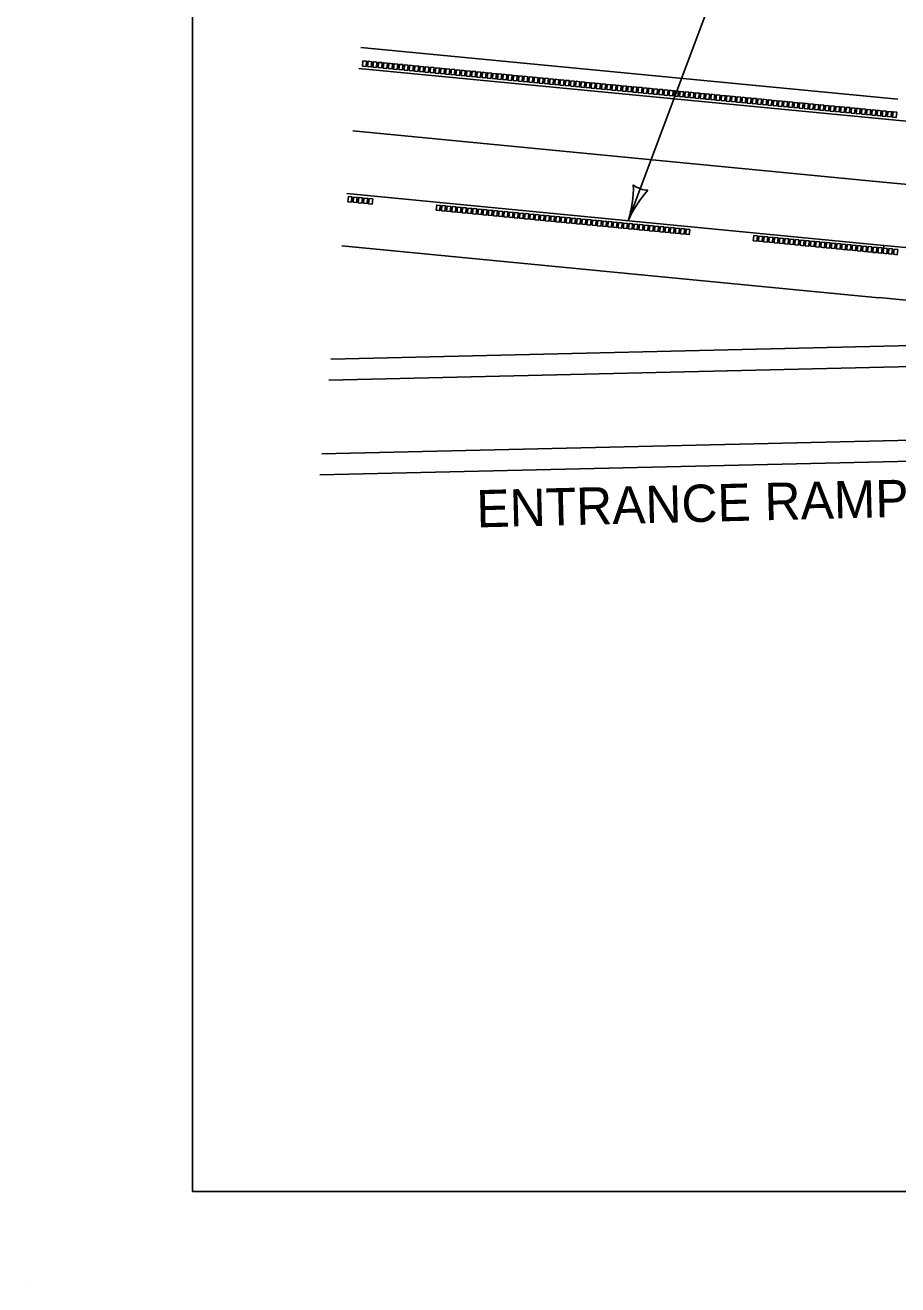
# Model space of a CAD drawing. Extents: x 49991.4 to 50021, y 49987.6 to 50011.4.
# Drawn here: x 49999.024 to 50000.896, y 49987.599 to 49990.3 of the extents above; entities that cross this region are included whole.
import ezdxf

# ---------------------------------------------------------------- set-up
doc = ezdxf.new("R2010")
doc.units = 0
for name, color, linetype in [('Level 1', 7, 'Continuous'), ('Level 2', 7, 'Continuous'), ('Level 3', 7, 'Continuous')]:
    doc.layers.add(name, color=color, linetype=linetype)

msp = doc.modelspace()

# ---------------------------------------------------------------- linework, layer by layer
at = {"layer": 'Level 1'}
for p, q in [((49999.7445, 49990.2519), (50000.8963, 49990.141)), ((49999.7402, 49990.207), (50000.892, 49990.0962)), ((49999.7273, 49990.0728), (50000.8791, 49989.9618)), ((49999.7143, 49989.9384), (50000.8661, 49989.8274)), ((49999.7035, 49989.8264), (50000.8553, 49989.7154)), ((50000.8659, 49989.8216), (50000.8649, 49989.8105)), ((50000.8665, 49989.8274), (50000.8659, 49989.8216)), ((50000.8659, 49989.8216), (50000.8737, 49989.8209)), ((50000.8737, 49989.8209), (50000.8726, 49989.8097)), ((50000.8771, 49989.8206), (50000.876, 49989.8094)), ((50000.8771, 49989.8206), (50000.8848, 49989.8198)), ((50000.8848, 49989.8198), (50000.8838, 49989.8087)), ((50000.8882, 49989.8195), (50000.8871, 49989.8084)), ((50000.8882, 49989.8195), (50000.896, 49989.8188)), ((50000.896, 49989.8188), (50000.8949, 49989.8076)), ((50000.8649, 49989.8105), (50000.8726, 49989.8097)), ((50000.876, 49989.8094), (50000.8838, 49989.8087)), ((50000.8871, 49989.8084), (50000.8949, 49989.8076)), ((49999.6802, 49989.5838), (50001.8012, 49989.633)), ((49999.6759, 49989.5388), (50001.654, 49989.5846)), ((49999.6607, 49989.3808), (50001.6577, 49989.427)), ((49999.6563, 49989.3358), (50001.6587, 49989.382)), ((49999.0245, 49987.5988), (49999.0245, 49987.5988))]:
    msp.add_line(p, q, dxfattribs=at)
for points in [[(49999.3835, 49998.9992), (50016.7501, 49998.9992), (50016.7501, 49987.7988), (49999.3835, 49987.7988)], [(49999.748, 49990.2121), (49999.7557, 49990.2113), (49999.7568, 49990.2225), (49999.749, 49990.2232)], [(49999.7591, 49990.211), (49999.7669, 49990.2103), (49999.7679, 49990.2214), (49999.7602, 49990.2222)], [(49999.7702, 49990.2099), (49999.778, 49990.2092), (49999.7791, 49990.2203), (49999.7713, 49990.2211)], [(49999.7814, 49990.2089), (49999.7892, 49990.2081), (49999.7902, 49990.2193), (49999.7825, 49990.22)], [(49999.7925, 49990.2078), (49999.8003, 49990.2071), (49999.8014, 49990.2182), (49999.7936, 49990.219)], [(49999.8037, 49990.2067), (49999.8115, 49990.206), (49999.8125, 49990.2171), (49999.8048, 49990.2179)], [(49999.8148, 49990.2057), (49999.8226, 49990.2049), (49999.8237, 49990.2161), (49999.8159, 49990.2168)], [(49999.826, 49990.2046), (49999.8338, 49990.2038), (49999.8348, 49990.215), (49999.8271, 49990.2157)], [(49999.8371, 49990.2035), (49999.8449, 49990.2028), (49999.846, 49990.2139), (49999.8382, 49990.2147)], [(49999.8483, 49990.2024), (49999.8561, 49990.2017), (49999.8571, 49990.2128), (49999.8494, 49990.2136)], [(49999.8594, 49990.2014), (49999.8672, 49990.2006), (49999.8683, 49990.2118), (49999.8605, 49990.2125)], [(49999.8706, 49990.2003), (49999.8784, 49990.1995), (49999.8794, 49990.2107), (49999.8717, 49990.2114)], [(49999.8817, 49990.1992), (49999.8895, 49990.1985), (49999.8906, 49990.2096), (49999.8828, 49990.2104)], [(49999.8929, 49990.1982), (49999.9006, 49990.1974), (49999.9017, 49990.2086), (49999.894, 49990.2093)], [(49999.904, 49990.1971), (49999.9118, 49990.1963), (49999.9129, 49990.2075), (49999.9051, 49990.2082)], [(49999.9152, 49990.196), (49999.9229, 49990.1953), (49999.924, 49990.2064), (49999.9163, 49990.2072)], [(49999.9263, 49990.1949), (49999.9341, 49990.1942), (49999.9352, 49990.2053), (49999.9274, 49990.2061)], [(49999.9375, 49990.1939), (49999.9452, 49990.1931), (49999.9463, 49990.2043), (49999.9386, 49990.205)], [(49999.9486, 49990.1928), (49999.9564, 49990.192), (49999.9575, 49990.2032), (49999.9497, 49990.2039)], [(49999.9598, 49990.1917), (49999.9675, 49990.191), (49999.9686, 49990.2021), (49999.9608, 49990.2029)], [(49999.9709, 49990.1906), (49999.9787, 49990.1899), (49999.9798, 49990.201), (49999.972, 49990.2018)], [(49999.9821, 49990.1896), (49999.9898, 49990.1888), (49999.9909, 49990.2), (49999.9831, 49990.2007)], [(49999.9932, 49990.1885), (50000.001, 49990.1878), (50000.0021, 49990.1989), (49999.9943, 49990.1996)], [(50000.0044, 49990.1874), (50000.0121, 49990.1867), (50000.0132, 49990.1978), (50000.0054, 49990.1986)], [(50000.0155, 49990.1864), (50000.0233, 49990.1856), (50000.0244, 49990.1968), (50000.0166, 49990.1975)], [(50000.0267, 49990.1853), (50000.0344, 49990.1845), (50000.0355, 49990.1957), (50000.0277, 49990.1964)], [(50000.0378, 49990.1842), (50000.0456, 49990.1835), (50000.0467, 49990.1946), (50000.0389, 49990.1954)], [(50000.049, 49990.1831), (50000.0567, 49990.1824), (50000.0578, 49990.1935), (50000.05, 49990.1943)], [(50000.0601, 49990.1821), (50000.0679, 49990.1813), (50000.0689, 49990.1925), (50000.0612, 49990.1932)], [(50000.0713, 49990.181), (50000.079, 49990.1802), (50000.0801, 49990.1914), (50000.0723, 49990.1921)], [(50000.0824, 49990.1799), (50000.0902, 49990.1792), (50000.0912, 49990.1903), (50000.0835, 49990.1911)], [(50000.0936, 49990.1788), (50000.1013, 49990.1781), (50000.1024, 49990.1892), (50000.0946, 49990.19)], [(50000.1047, 49990.1778), (50000.1125, 49990.177), (50000.1135, 49990.1882), (50000.1058, 49990.1889)], [(50000.1159, 49990.1767), (50000.1236, 49990.176), (50000.1247, 49990.1871), (50000.1169, 49990.1879)], [(50000.127, 49990.1756), (50000.1348, 49990.1749), (50000.1358, 49990.186), (50000.1281, 49990.1868)], [(50000.1382, 49990.1746), (50000.1459, 49990.1738), (50000.147, 49990.185), (50000.1392, 49990.1857)], [(50000.1493, 49990.1735), (50000.1571, 49990.1727), (50000.1581, 49990.1839), (50000.1504, 49990.1846)], [(50000.1604, 49990.1724), (50000.1682, 49990.1717), (50000.1693, 49990.1828), (50000.1615, 49990.1836)], [(50000.1716, 49990.1713), (50000.1794, 49990.1706), (50000.1804, 49990.1817), (50000.1727, 49990.1825)], [(50000.1827, 49990.1703), (50000.1905, 49990.1695), (50000.1916, 49990.1807), (50000.1838, 49990.1814)], [(50000.1939, 49990.1692), (50000.2017, 49990.1684), (50000.2027, 49990.1796), (50000.195, 49990.1803)], [(50000.205, 49990.1681), (50000.2128, 49990.1674), (50000.2139, 49990.1785), (50000.2061, 49990.1793)], [(50000.2162, 49990.167), (50000.224, 49990.1663), (50000.225, 49990.1774), (50000.2173, 49990.1782)], [(50000.2273, 49990.166), (50000.2351, 49990.1652), (50000.2362, 49990.1764), (50000.2284, 49990.1771)], [(50000.2385, 49990.1649), (50000.2463, 49990.1642), (50000.2473, 49990.1753), (50000.2396, 49990.1761)], [(50000.2496, 49990.1638), (50000.2574, 49990.1631), (50000.2585, 49990.1742), (50000.2507, 49990.175)], [(50000.2608, 49990.1628), (50000.2685, 49990.162), (50000.2696, 49990.1732), (50000.2619, 49990.1739)], [(50000.2719, 49990.1617), (50000.2797, 49990.1609), (50000.2808, 49990.1721), (50000.273, 49990.1728)], [(50000.2831, 49990.1606), (50000.2908, 49990.1599), (50000.2919, 49990.171), (50000.2842, 49990.1718)], [(50000.2942, 49990.1595), (50000.302, 49990.1588), (50000.3031, 49990.1699), (50000.2953, 49990.1707)], [(50000.3054, 49990.1585), (50000.3131, 49990.1577), (50000.3142, 49990.1689), (50000.3065, 49990.1696)], [(50000.3165, 49990.1574), (50000.3243, 49990.1566), (50000.3254, 49990.1678), (50000.3176, 49990.1685)], [(50000.3277, 49990.1563), (50000.3354, 49990.1556), (50000.3365, 49990.1667), (50000.3288, 49990.1675)], [(50000.3388, 49990.1553), (50000.3466, 49990.1545), (50000.3477, 49990.1657), (50000.3399, 49990.1664)], [(50000.35, 49990.1542), (50000.3577, 49990.1534), (50000.3588, 49990.1646), (50000.351, 49990.1653)], [(50000.3611, 49990.1531), (50000.3689, 49990.1524), (50000.37, 49990.1635), (50000.3622, 49990.1643)], [(50000.3723, 49990.152), (50000.38, 49990.1513), (50000.3811, 49990.1624), (50000.3733, 49990.1632)], [(50000.3834, 49990.151), (50000.3912, 49990.1502), (50000.3923, 49990.1614), (50000.3845, 49990.1621)], [(50000.3946, 49990.1499), (50000.4023, 49990.1491), (50000.4034, 49990.1603), (50000.3956, 49990.161)], [(50000.4057, 49990.1488), (50000.4135, 49990.1481), (50000.4146, 49990.1592), (50000.4068, 49990.16)], [(50000.4169, 49990.1477), (50000.4246, 49990.147), (50000.4257, 49990.1581), (50000.4179, 49990.1589)], [(50000.428, 49990.1467), (50000.4358, 49990.1459), (50000.4369, 49990.1571), (50000.4291, 49990.1578)], [(50000.4392, 49990.1456), (50000.4469, 49990.1449), (50000.448, 49990.156), (50000.4402, 49990.1567)], [(50000.4503, 49990.1445), (50000.4581, 49990.1438), (50000.4591, 49990.1549), (50000.4514, 49990.1557)], [(50000.4615, 49990.1435), (50000.4692, 49990.1427), (50000.4703, 49990.1539), (50000.4625, 49990.1546)], [(50000.4726, 49990.1424), (50000.4804, 49990.1416), (50000.4814, 49990.1528), (50000.4737, 49990.1535)], [(50000.4838, 49990.1413), (50000.4915, 49990.1406), (50000.4926, 49990.1517), (50000.4848, 49990.1525)], [(50000.4949, 49990.1402), (50000.5027, 49990.1395), (50000.5037, 49990.1506), (50000.496, 49990.1514)], [(50000.5061, 49990.1392), (50000.5138, 49990.1384), (50000.5149, 49990.1496), (50000.5071, 49990.1503)], [(50000.5172, 49990.1381), (50000.525, 49990.1373), (50000.526, 49990.1485), (50000.5183, 49990.1492)], [(50000.5283, 49990.137), (50000.5361, 49990.1363), (50000.5372, 49990.1474), (50000.5294, 49990.1482)], [(50000.5395, 49990.1359), (50000.5473, 49990.1352), (50000.5483, 49990.1463), (50000.5406, 49990.1471)], [(50000.5506, 49990.1349), (50000.5584, 49990.1341), (50000.5595, 49990.1453), (50000.5517, 49990.146)], [(50000.5618, 49990.1338), (50000.5696, 49990.1331), (50000.5706, 49990.1442), (50000.5629, 49990.145)], [(50000.5729, 49990.1327), (50000.5807, 49990.132), (50000.5818, 49990.1431), (50000.574, 49990.1439)], [(50000.5841, 49990.1317), (50000.5919, 49990.1309), (50000.5929, 49990.1421), (50000.5852, 49990.1428)], [(50000.5952, 49990.1306), (50000.603, 49990.1298), (50000.6041, 49990.141), (50000.5963, 49990.1417)], [(50000.6064, 49990.1295), (50000.6142, 49990.1288), (50000.6152, 49990.1399), (50000.6075, 49990.1407)], [(50000.6175, 49990.1284), (50000.6253, 49990.1277), (50000.6264, 49990.1388), (50000.6186, 49990.1396)], [(50000.6287, 49990.1274), (50000.6365, 49990.1266), (50000.6375, 49990.1378), (50000.6298, 49990.1385)], [(50000.6398, 49990.1263), (50000.6476, 49990.1255), (50000.6487, 49990.1367), (50000.6409, 49990.1374)], [(50000.651, 49990.1252), (50000.6587, 49990.1245), (50000.6598, 49990.1356), (50000.6521, 49990.1364)], [(50000.6621, 49990.1242), (50000.6699, 49990.1234), (50000.671, 49990.1346), (50000.6632, 49990.1353)], [(50000.6733, 49990.1231), (50000.681, 49990.1223), (50000.6821, 49990.1335), (50000.6744, 49990.1342)], [(50000.6844, 49990.122), (50000.6922, 49990.1213), (50000.6933, 49990.1324), (50000.6855, 49990.1332)], [(50000.6956, 49990.1209), (50000.7033, 49990.1202), (50000.7044, 49990.1313), (50000.6967, 49990.1321)], [(50000.7067, 49990.1199), (50000.7145, 49990.1191), (50000.7156, 49990.1303), (50000.7078, 49990.131)], [(50000.7179, 49990.1188), (50000.7256, 49990.118), (50000.7267, 49990.1292), (50000.7189, 49990.1299)], [(50000.729, 49990.1177), (50000.7368, 49990.117), (50000.7379, 49990.1281), (50000.7301, 49990.1289)], [(50000.7402, 49990.1166), (50000.7479, 49990.1159), (50000.749, 49990.127), (50000.7412, 49990.1278)], [(50000.7513, 49990.1156), (50000.7591, 49990.1148), (50000.7602, 49990.126), (50000.7524, 49990.1267)], [(50000.7625, 49990.1145), (50000.7702, 49990.1138), (50000.7713, 49990.1249), (50000.7635, 49990.1256)], [(50000.7736, 49990.1134), (50000.7814, 49990.1127), (50000.7825, 49990.1238), (50000.7747, 49990.1246)], [(50000.7848, 49990.1124), (50000.7925, 49990.1116), (50000.7936, 49990.1228), (50000.7858, 49990.1235)], [(50000.7959, 49990.1113), (50000.8037, 49990.1105), (50000.8048, 49990.1217), (50000.797, 49990.1224)], [(50000.8071, 49990.1102), (50000.8148, 49990.1095), (50000.8159, 49990.1206), (50000.8081, 49990.1214)], [(50000.8182, 49990.1091), (50000.826, 49990.1084), (50000.827, 49990.1195), (50000.8193, 49990.1203)], [(50000.8294, 49990.1081), (50000.8371, 49990.1073), (50000.8382, 49990.1185), (50000.8304, 49990.1192)], [(50000.8405, 49990.107), (50000.8483, 49990.1062), (50000.8493, 49990.1174), (50000.8416, 49990.1181)], [(50000.8517, 49990.1059), (50000.8594, 49990.1052), (50000.8605, 49990.1163), (50000.8527, 49990.1171)], [(50000.8628, 49990.1048), (50000.8706, 49990.1041), (50000.8716, 49990.1152), (50000.8639, 49990.116)], [(50000.874, 49990.1038), (50000.8817, 49990.103), (50000.8828, 49990.1142), (50000.875, 49990.1149)], [(50000.8851, 49990.1027), (50000.8929, 49990.102), (50000.8939, 49990.1131), (50000.8862, 49990.1139)], [(49999.7166, 49989.9212), (49999.7244, 49989.9204), (49999.7254, 49989.9316), (49999.7177, 49989.9323)], [(49999.7278, 49989.9201), (49999.7355, 49989.9193), (49999.7366, 49989.9305), (49999.7288, 49989.9312)], [(49999.7389, 49989.919), (49999.7467, 49989.9183), (49999.7477, 49989.9294), (49999.74, 49989.9302)], [(49999.7501, 49989.9179), (49999.7578, 49989.9172), (49999.7589, 49989.9283), (49999.7511, 49989.9291)], [(49999.7612, 49989.9169), (49999.769, 49989.9161), (49999.77, 49989.9273), (49999.7623, 49989.928)], [(49999.9061, 49989.9029), (49999.9139, 49989.9021), (49999.915, 49989.9133), (49999.9072, 49989.914)], [(49999.9173, 49989.9018), (49999.925, 49989.9011), (49999.9261, 49989.9122), (49999.9184, 49989.913)], [(49999.9284, 49989.9007), (49999.9362, 49989.9), (49999.9373, 49989.9111), (49999.9295, 49989.9119)], [(49999.9396, 49989.8997), (49999.9473, 49989.8989), (49999.9484, 49989.9101), (49999.9407, 49989.9108)], [(49999.9507, 49989.8986), (49999.9585, 49989.8978), (49999.9596, 49989.909), (49999.9518, 49989.9097)], [(49999.9619, 49989.8975), (49999.9696, 49989.8968), (49999.9707, 49989.9079), (49999.9629, 49989.9087)], [(49999.973, 49989.8964), (49999.9808, 49989.8957), (49999.9819, 49989.9068), (49999.9741, 49989.9076)], [(49999.9842, 49989.8954), (49999.9919, 49989.8946), (49999.993, 49989.9058), (49999.9852, 49989.9065)], [(49999.9953, 49989.8943), (50000.0031, 49989.8935), (50000.0042, 49989.9047), (49999.9964, 49989.9054)], [(50000.0065, 49989.8932), (50000.0142, 49989.8925), (50000.0153, 49989.9036), (50000.0075, 49989.9044)], [(50000.0176, 49989.8921), (50000.0254, 49989.8914), (50000.0265, 49989.9025), (50000.0187, 49989.9033)], [(50000.0288, 49989.8911), (50000.0365, 49989.8903), (50000.0376, 49989.9015), (50000.0298, 49989.9022)], [(50000.0399, 49989.89), (50000.0477, 49989.8892), (50000.0488, 49989.9004), (50000.041, 49989.9011)], [(50000.0511, 49989.8889), (50000.0588, 49989.8882), (50000.0599, 49989.8993), (50000.0521, 49989.9001)], [(50000.0622, 49989.8878), (50000.07, 49989.8871), (50000.071, 49989.8982), (50000.0633, 49989.899)], [(50000.0734, 49989.8868), (50000.0811, 49989.886), (50000.0822, 49989.8972), (50000.0744, 49989.8979)], [(50000.0845, 49989.8857), (50000.0923, 49989.885), (50000.0933, 49989.8961), (50000.0856, 49989.8968)], [(50000.0957, 49989.8846), (50000.1034, 49989.8839), (50000.1045, 49989.895), (50000.0967, 49989.8958)], [(50000.1068, 49989.8836), (50000.1146, 49989.8828), (50000.1156, 49989.894), (50000.1079, 49989.8947)], [(50000.118, 49989.8825), (50000.1257, 49989.8817), (50000.1268, 49989.8929), (50000.119, 49989.8936)], [(50000.1291, 49989.8814), (50000.1369, 49989.8807), (50000.1379, 49989.8918), (50000.1302, 49989.8926)], [(50000.1402, 49989.8803), (50000.148, 49989.8796), (50000.1491, 49989.8907), (50000.1413, 49989.8915)], [(50000.1514, 49989.8793), (50000.1592, 49989.8785), (50000.1602, 49989.8897), (50000.1525, 49989.8904)], [(50000.1625, 49989.8782), (50000.1703, 49989.8774), (50000.1714, 49989.8886), (50000.1636, 49989.8893)], [(50000.1737, 49989.8771), (50000.1815, 49989.8764), (50000.1825, 49989.8875), (50000.1748, 49989.8883)], [(50000.1848, 49989.876), (50000.1926, 49989.8753), (50000.1937, 49989.8864), (50000.1859, 49989.8872)], [(50000.196, 49989.875), (50000.2038, 49989.8742), (50000.2048, 49989.8854), (50000.1971, 49989.8861)], [(50000.2071, 49989.8739), (50000.2149, 49989.8731), (50000.216, 49989.8843), (50000.2082, 49989.885)], [(50000.2183, 49989.8728), (50000.2261, 49989.8721), (50000.2271, 49989.8832), (50000.2194, 49989.884)], [(50000.2294, 49989.8717), (50000.2372, 49989.871), (50000.2383, 49989.8821), (50000.2305, 49989.8829)], [(50000.2406, 49989.8707), (50000.2483, 49989.8699), (50000.2494, 49989.8811), (50000.2417, 49989.8818)], [(50000.2517, 49989.8696), (50000.2595, 49989.8688), (50000.2606, 49989.88), (50000.2528, 49989.8807)], [(50000.2629, 49989.8685), (50000.2706, 49989.8678), (50000.2717, 49989.8789), (50000.264, 49989.8797)], [(50000.274, 49989.8674), (50000.2818, 49989.8667), (50000.2829, 49989.8778), (50000.2751, 49989.8786)], [(50000.2852, 49989.8664), (50000.2929, 49989.8656), (50000.294, 49989.8768), (50000.2863, 49989.8775)], [(50000.2963, 49989.8653), (50000.3041, 49989.8645), (50000.3052, 49989.8757), (50000.2974, 49989.8764)], [(50000.3075, 49989.8642), (50000.3152, 49989.8635), (50000.3163, 49989.8746), (50000.3085, 49989.8754)], [(50000.3186, 49989.8631), (50000.3264, 49989.8624), (50000.3275, 49989.8735), (50000.3197, 49989.8743)], [(50000.3298, 49989.8621), (50000.3375, 49989.8613), (50000.3386, 49989.8725), (50000.3308, 49989.8732)], [(50000.3409, 49989.861), (50000.3487, 49989.8602), (50000.3498, 49989.8714), (50000.342, 49989.8721)], [(50000.3521, 49989.8599), (50000.3598, 49989.8592), (50000.3609, 49989.8703), (50000.3531, 49989.8711)], [(50000.3632, 49989.8588), (50000.371, 49989.8581), (50000.3721, 49989.8692), (50000.3643, 49989.87)], [(50000.3744, 49989.8578), (50000.3821, 49989.857), (50000.3832, 49989.8682), (50000.3754, 49989.8689)], [(50000.3855, 49989.8567), (50000.3933, 49989.8559), (50000.3944, 49989.8671), (50000.3866, 49989.8678)], [(50000.3967, 49989.8556), (50000.4044, 49989.8549), (50000.4055, 49989.866), (50000.3977, 49989.8668)], [(50000.4078, 49989.8545), (50000.4156, 49989.8538), (50000.4166, 49989.8649), (50000.4089, 49989.8657)], [(50000.419, 49989.8535), (50000.4267, 49989.8527), (50000.4278, 49989.8639), (50000.42, 49989.8646)], [(50000.4301, 49989.8524), (50000.4379, 49989.8516), (50000.4389, 49989.8628), (50000.4312, 49989.8635)], [(50000.4413, 49989.8513), (50000.449, 49989.8506), (50000.4501, 49989.8617), (50000.4423, 49989.8625)], [(50000.5862, 49989.8374), (50000.5939, 49989.8366), (50000.595, 49989.8478), (50000.5873, 49989.8485)], [(50000.5973, 49989.8363), (50000.6051, 49989.8355), (50000.6062, 49989.8467), (50000.5984, 49989.8474)], [(50000.6085, 49989.8352), (50000.6162, 49989.8345), (50000.6173, 49989.8456), (50000.6096, 49989.8464)], [(50000.6196, 49989.8341), (50000.6274, 49989.8334), (50000.6285, 49989.8445), (50000.6207, 49989.8453)], [(50000.6308, 49989.8331), (50000.6385, 49989.8323), (50000.6396, 49989.8435), (50000.6318, 49989.8442)], [(50000.6419, 49989.832), (50000.6497, 49989.8312), (50000.6508, 49989.8424), (50000.643, 49989.8431)], [(50000.6531, 49989.8309), (50000.6608, 49989.8302), (50000.6619, 49989.8413), (50000.6541, 49989.8421)], [(50000.6642, 49989.8298), (50000.672, 49989.8291), (50000.6731, 49989.8402), (50000.6653, 49989.841)], [(50000.6754, 49989.8288), (50000.6831, 49989.828), (50000.6842, 49989.8392), (50000.6764, 49989.8399)], [(50000.6865, 49989.8277), (50000.6943, 49989.8269), (50000.6954, 49989.8381), (50000.6876, 49989.8388)], [(50000.6977, 49989.8266), (50000.7054, 49989.8259), (50000.7065, 49989.837), (50000.6987, 49989.8378)], [(50000.7088, 49989.8255), (50000.7166, 49989.8248), (50000.7177, 49989.8359), (50000.7099, 49989.8367)], [(50000.72, 49989.8245), (50000.7277, 49989.8237), (50000.7288, 49989.8349), (50000.721, 49989.8356)], [(50000.7311, 49989.8234), (50000.7389, 49989.8226), (50000.7399, 49989.8338), (50000.7322, 49989.8345)], [(50000.7423, 49989.8223), (50000.75, 49989.8216), (50000.7511, 49989.8327), (50000.7433, 49989.8335)], [(50000.7534, 49989.8212), (50000.7612, 49989.8205), (50000.7622, 49989.8316), (50000.7545, 49989.8324)], [(50000.7646, 49989.8202), (50000.7723, 49989.8194), (50000.7734, 49989.8306), (50000.7656, 49989.8313)], [(50000.7757, 49989.8191), (50000.7835, 49989.8183), (50000.7845, 49989.8295), (50000.7768, 49989.8302)], [(50000.7869, 49989.818), (50000.7946, 49989.8173), (50000.7957, 49989.8284), (50000.7879, 49989.8292)], [(50000.798, 49989.8169), (50000.8058, 49989.8162), (50000.8068, 49989.8273), (50000.7991, 49989.8281)], [(50000.8091, 49989.8159), (50000.8169, 49989.8151), (50000.818, 49989.8263), (50000.8102, 49989.827)], [(50000.8203, 49989.8148), (50000.8281, 49989.814), (50000.8291, 49989.8252), (50000.8214, 49989.8259)], [(50000.8314, 49989.8137), (50000.8392, 49989.813), (50000.8403, 49989.8241), (50000.8325, 49989.8249)], [(50000.8426, 49989.8126), (50000.8504, 49989.8119), (50000.8514, 49989.823), (50000.8437, 49989.8238)], [(50000.8537, 49989.8116), (50000.8615, 49989.8108), (50000.8626, 49989.822), (50000.8548, 49989.8227)]]:
    msp.add_lwpolyline(points, close=True, dxfattribs=at)
for radius, end in [(52.2601, 270), (52.3951, 270), (52.5301, 270), (52.6426, 265.53343)]:
    msp.add_arc((50005.9009, 50042.1157), radius, 264.5, end, dxfattribs=at)
at = {"layer": 'Level 3'}
msp.add_line((50000.318, 49989.8802), (50000.5133, 49990.4024), dxfattribs=at)
for centre, radius, start, end in [((50000.1067, 49989.9495), 0.2223, 341.8488, 2.0323), ((50000.3629, 49990.0003), 0.0548, 231.6271, 267.3495), ((50000.5319, 49989.7879), 0.233, 137.4111, 156.661)]:
    msp.add_arc(centre, radius, start, end, dxfattribs=at)

# ---------------------------------------------------------------- texts
at = {"layer": 'Level 2'}
msp.add_text('ENTRANCE RAMP', height=0.08, rotation=1.422, dxfattribs=at).set_placement((49999.9934, 49989.2227))

doc.saveas('drawing.dxf')
